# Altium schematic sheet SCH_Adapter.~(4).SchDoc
size A
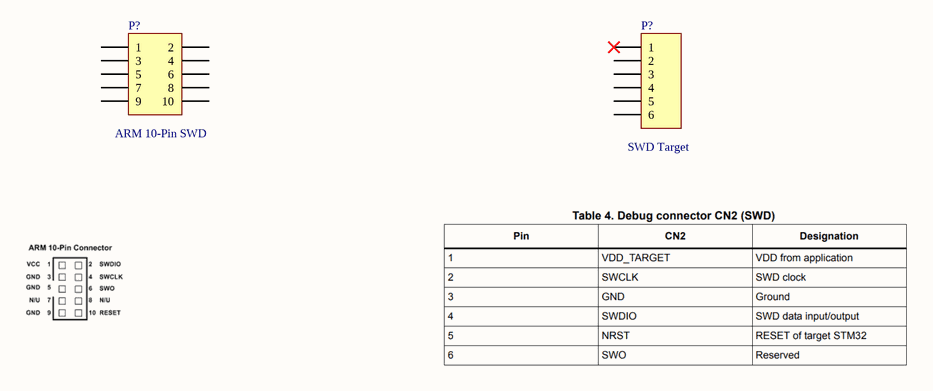
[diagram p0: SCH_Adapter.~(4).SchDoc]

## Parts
(Parts that share a designator on the sheet are numbered #1, #2 ... from top to bottom, then left to right.)
P?#1  ARM 10-Pin SWD  [HDR2X5]
P?#2  SWD Target  [HDR1X6]

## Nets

Not connected (* = marked no-connect by the designer): P?#1 1 2 3 4 5 6 7 8 9 10; P?#2 1* 2 3 4 5 6

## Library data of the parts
P?#1 = Header 5X2: Header, 5-Pin, Dual row
P?#2 = Header 6: Header, 6-Pin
